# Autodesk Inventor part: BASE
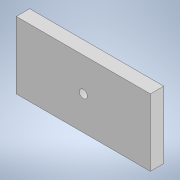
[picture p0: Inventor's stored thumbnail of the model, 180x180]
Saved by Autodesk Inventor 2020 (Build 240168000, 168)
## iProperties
Created: 2023-07
Part Number: BASE
Material: 일반
Document SubType Name: Modeling
Designer: chae-won
Density: 1 g/cm^3
Appearance: 기본값
Author: chae-won
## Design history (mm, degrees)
sketch "스케치1"
  geometry: L1 (-50, 25)-(50, 25); L2 (50, 25)-(50, -25); L3 (50, -25)-(-50, -25); L4 (-50, -25)-(-50, 25); L5 (-50, 25)-(50, -25); L6 (50, 25)-(-50, -25); 1 further point
  constraints: 12 end point, 2 midpoint, 2 parallel, 1 horizontal, 1 perpendicular
  dimensions: "d0" = 50 distance between parallel lines of L1 L3; "d1" = 100 distance between parallel lines of L4 L2
extrude "돌출1" new body sketch "스케치1" distance "d2" = 10; taper "d3" = 0 deg
sketch "스케치2"
  geometry: 1 further point
hole "구멍1" sketch "스케치2" at (0, 0) diameter "d4" = 5; stored, may be unused: countersink angle "d8" = 82 deg, drill point angle "d10" = 118 deg; dims "d5" = 6, "d6" = 6, "d7" = 8, "d9" = 8
node "솔리드1"
feature "A9D066F2-1C7D-4E18-AEED-F7BC21143FA4" dims "d4" = 5, "d5" = 6, "d6" = 6, "d7" = 8, "d8" = 82 deg, "d9" = 8, "d10" = 118 deg
